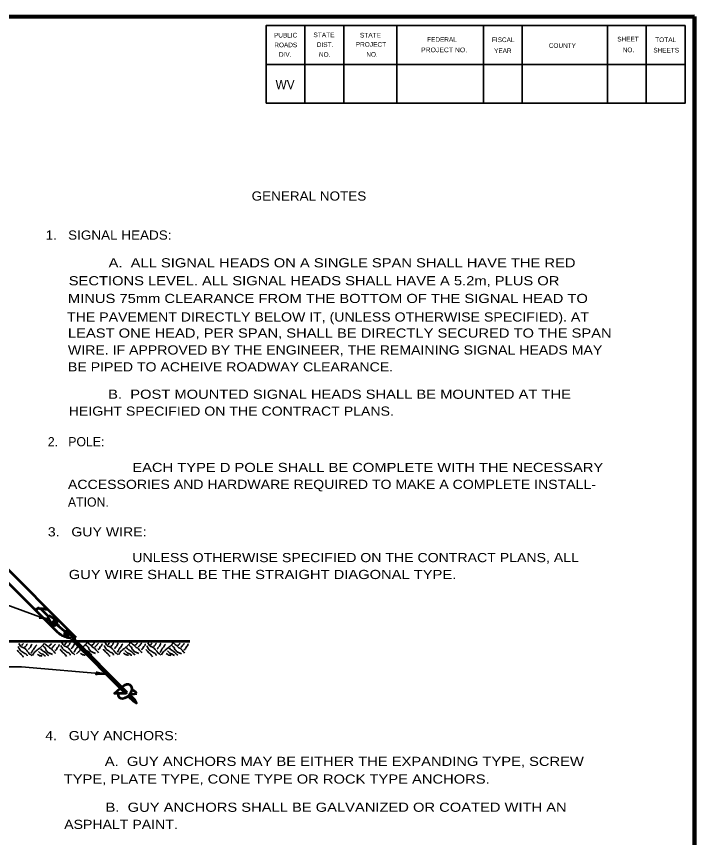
# Model space of a CAD drawing. Extents: x 14808 to 15663, y 10944 to 11488.
# Drawn here: x 15435 to 15656.9, y 11213.1 to 11481.7 of the extents above; entities that cross this region are included whole.
import ezdxf
from ezdxf.enums import TextEntityAlignment as Align

# ---------------------------------------------------------------- set-up
doc = ezdxf.new("R2010")
doc.units = 0
doc.header["$LTSCALE"] = 1.2
doc.layers.add('1', color=7, linetype='Continuous', lineweight=53)
doc.layers.add('61', color=7, linetype='Continuous', lineweight=35)

msp = doc.modelspace()

# ---------------------------------------------------------------- linework, layer by layer
at = {"layer": '1', "lineweight": 158}
msp.add_line((15656.868, 10955.64), (15656.868, 11481.74), dxfattribs=at)
at = {"layer": '1', "lineweight": 13}
msp.add_line((15656.868, 10955.64), (15656.868, 11481.74), dxfattribs=at)
at = {"layer": '1'}
for p, q in [((15428.058, 11304.925), (15454.362, 11278.621)), ((15430.179, 11298.561), (15447.998, 11280.742)), ((15442.831, 11288.076), (15445.377, 11285.53)), ((15445.165, 11285.318), (15445.589, 11285.742)), ((15446.438, 11283.196), (15445.165, 11285.318)), ((15447.71, 11284.469), (15445.589, 11285.742)), ((15447.922, 11284.681), (15446.225, 11282.984)), ((15448.347, 11284.257), (15446.65, 11282.56)), ((15448.347, 11284.257), (15447.922, 11284.681)), ((15446.65, 11282.56), (15446.225, 11282.984)), ((15451.386, 11280.077), (15447.463, 11283.368)), ((15448.093, 11282.84), (15448.977, 11282.428)), ((15452.27, 11279.179), (15451.575, 11279.365)), ((15452.27, 11279.179), (15452.084, 11279.874)), ((15453.326, 11278.561), (15471.145, 11260.742)), ((15267.529, 11277.361), (15491.726, 11277.361)), ((15471.993, 11259.893), (15474.357, 11260.31)), ((15471.993, 11259.893), (15473.69, 11258.196))]:
    msp.add_line(p, q, dxfattribs=at)
at = {"layer": '1', "lineweight": 35}
for p, q in [((15445.843, 11284.188), (15421.629, 11293.001)), ((15436.634, 11269.019), (15431.481, 11269.019)), ((15436.634, 11269.019), (15464.409, 11266.59))]:
    msp.add_line(p, q, dxfattribs=at)
at = {"layer": '1', "lineweight": 158}
msp.add_lwpolyline([(15656.868, 11481.74), (14865.168, 11481.64), (14865.268, 10955.64)], dxfattribs=at)
at = {"layer": '1'}
for points in [[(15452.882, 11278.117), (15470.701, 11260.298), (15467.101, 11260.298), (15469.002, 11261.974)], [(15471.549, 11259.449), (15473.246, 11257.752), (15474.317, 11257.126), (15473.69, 11258.196)]]:
    msp.add_lwpolyline(points, dxfattribs=at)
for centre, radius, start, end in [((15447.44, 11283.466), 0.904, 230.20411, 39.79589), ((15453.121, 11285.504), 6.994, 222.90975, 254.56822), ((15451.738, 11279.712), 1.064, 22.37581, 247.62419), ((15451.676, 11279.773), 0.42, 13.9871, 256.0129), ((15452.369, 11281.867), 3.305, 251.74116, 268.96028), ((15451.536, 11276.978), 1.762, 40.24577, 64.00426), ((15450.12, 11279.196), 2.761, 358.69833, 19.49446), ((15454.464, 11279.906), 1.762, 205.99574, 229.75423), ((15453.121, 11285.504), 6.994, 272.0576, 280.22035), ((15470.684, 11260.758), 0.461, 272.04039, 357.95961), ((15472.243, 11258.964), 2.506, 32.48706, 78.42981)]:
    msp.add_arc(centre, radius, start, end, dxfattribs=at)
at = {"layer": '1', "lineweight": 40}
for centre, major_axis, ratio, start_param, end_param in [((15444.499, 11284.324), (2.078, -0.557), 0.122415, 0.8963533, 3.1415927), ((15444.499, 11284.324), (2.078, -0.557), 0.122415, 0.8963533, 3.1415927), ((15444.666, 11284.886), (-1.909, 0.919), 0.07063, 6.2823074, 8.5597026), ((15444.666, 11284.886), (-1.909, 0.919), 0.07063, 6.2823074, 8.5597026), ((15463.076, 11266.374), (2.151, 0), 0.122415, 0.8963533, 3.1415927), ((15463.092, 11266.96), (-2.081, 0.394), 0.07063, 6.2823074, 8.5597026)]:
    msp.add_ellipse(centre, major_axis=major_axis, ratio=ratio, start_param=start_param, end_param=end_param, dxfattribs=at)
at = {"layer": '1'}
msp.add_ellipse((15470.499, 11260.944), major_axis=(-1.919, -1.919), ratio=0.663245, start_param=5.5824837, end_param=10.8796755, dxfattribs=at)
msp.add_spline([(15441.21, 11287.53), (15441.482, 11287.933), (15441.643, 11287.797), (15441.965, 11288.119), (15442.138, 11288.28), (15442.534, 11288.119), (15443.041, 11288.045), (15443.301, 11288.082), (15443.672, 11287.872), (15443.87, 11288.107), (15444.266, 11287.971), (15444.625, 11287.872), (15445.028, 11287.954)], degree=3, dxfattribs=at)
at = {"layer": '1', "lineweight": 35}
for points in [[(15435.808, 11276.655), (15436.575, 11275.58), (15437.574, 11275.119), (15438.188, 11274.505), (15438.495, 11274.121), (15438.879, 11273.66), (15439.186, 11273.276), (15439.646, 11273.046), (15440.03, 11272.586)], [(15437.19, 11276.569), (15437.074, 11276.415), (15437.036, 11276.415), (15436.959, 11276.338), (15436.767, 11275.993), (15436.729, 11275.916)], [(15438.61, 11276.53), (15438.38, 11276.338), (15438.303, 11276.146), (15438.226, 11275.916), (15438.072, 11275.762), (15437.996, 11275.686), (15437.65, 11275.417)], [(15440.107, 11276.415), (15439.877, 11276.185), (15439.723, 11275.801), (15439.531, 11275.417), (15439.109, 11274.956), (15438.955, 11274.726), (15438.879, 11274.611)], [(15441.604, 11276.185), (15441.258, 11275.801), (15441.067, 11275.379), (15440.76, 11275.033), (15440.529, 11274.688), (15440.299, 11274.419), (15440.184, 11274.15), (15440.03, 11273.881), (15439.838, 11273.498)], [(15443.907, 11276.655), (15443.907, 11276.501), (15443.83, 11276.271), (15443.677, 11276.117), (15443.523, 11275.964), (15443.216, 11275.657), (15442.986, 11275.426), (15442.295, 11274.889), (15441.911, 11274.582), (15441.143, 11273.968), (15440.836, 11273.66), (15440.683, 11273.43), (15440.452, 11273.123), (15440.222, 11272.739)], [(15444.176, 11276.616), (15444.79, 11276.079), (15445.328, 11275.618), (15446.249, 11274.927), (15446.479, 11274.85), (15446.71, 11274.543), (15447.093, 11274.083), (15447.554, 11273.622), (15447.784, 11273.315)], [(15445.558, 11275.762), (15446.095, 11276.146), (15446.21, 11276.3), (15446.402, 11276.569)], [(15446.594, 11275.225), (15447.017, 11275.532), (15447.285, 11275.916), (15447.362, 11276.031), (15447.516, 11276.185), (15447.746, 11276.453)], [(15447.592, 11274.342), (15448.13, 11274.649), (15448.207, 11274.995), (15448.706, 11275.609), (15448.859, 11275.801), (15448.936, 11276.108), (15448.974, 11276.262)], [(15449.598, 11275.983), (15449.751, 11275.522), (15450.058, 11275.023), (15450.442, 11274.524), (15450.826, 11274.294), (15451.479, 11273.833), (15452.515, 11273.142), (15452.553, 11272.835)], [(15449.866, 11276.952), (15450.634, 11275.877), (15451.632, 11275.416), (15452.246, 11274.802), (15452.553, 11274.418), (15452.937, 11273.957), (15453.244, 11273.574), (15453.705, 11273.343), (15454.089, 11272.882)], [(15451.248, 11276.866), (15451.133, 11276.712), (15451.095, 11276.712), (15451.018, 11276.635), (15450.826, 11276.29), (15450.788, 11276.213)], [(15452.669, 11276.827), (15452.438, 11276.635), (15452.361, 11276.443), (15452.285, 11276.213), (15452.131, 11276.059), (15452.054, 11275.983), (15451.709, 11275.714)], [(15454.166, 11276.712), (15453.935, 11276.482), (15453.782, 11276.098), (15453.59, 11275.714), (15453.168, 11275.253), (15453.014, 11275.023), (15452.937, 11274.908)], [(15457.966, 11276.952), (15457.966, 11276.798), (15457.889, 11276.568), (15457.736, 11276.414), (15457.582, 11276.261), (15457.275, 11275.954), (15457.045, 11275.723), (15456.742, 11275.488)], [(15457.736, 11276.021), (15457.966, 11275.868), (15458.196, 11275.676), (15458.619, 11275.138), (15458.657, 11274.793), (15458.964, 11274.524), (15459.079, 11274.332), (15459.847, 11273.756), (15460.308, 11273.603), (15460.423, 11273.526), (15460.845, 11273.334)], [(15458.235, 11276.913), (15458.849, 11276.376), (15459.386, 11275.915), (15460.308, 11275.224), (15460.538, 11275.147), (15460.768, 11274.84), (15461.152, 11274.38), (15461.613, 11273.919), (15461.843, 11273.612)], [(15459.617, 11276.059), (15460.154, 11276.443), (15460.269, 11276.597), (15460.461, 11276.866)], [(15460.653, 11275.522), (15461.075, 11275.829), (15461.344, 11276.213), (15461.421, 11276.328), (15461.574, 11276.482), (15461.805, 11276.75)], [(15461.651, 11274.639), (15462.189, 11274.946), (15462.265, 11275.292), (15462.764, 11275.906), (15462.918, 11276.098), (15462.995, 11276.405), (15463.033, 11276.559)], [(15463.755, 11275.983), (15463.909, 11275.522), (15464.216, 11275.023), (15464.6, 11274.524), (15464.984, 11274.294), (15465.636, 11273.833), (15466.673, 11273.142), (15466.711, 11272.835)], [(15464.024, 11276.952), (15464.792, 11275.877), (15465.79, 11275.416), (15466.404, 11274.802), (15466.711, 11274.418), (15467.095, 11273.957), (15467.402, 11273.574), (15467.863, 11273.343), (15468.247, 11272.882)], [(15465.406, 11276.866), (15465.291, 11276.712), (15465.252, 11276.712), (15465.176, 11276.635), (15464.984, 11276.29), (15464.945, 11276.213)], [(15466.826, 11276.827), (15466.596, 11276.635), (15466.519, 11276.443), (15466.442, 11276.213), (15466.289, 11276.059), (15466.212, 11275.983), (15465.866, 11275.714)], [(15468.323, 11276.712), (15468.093, 11276.482), (15467.939, 11276.098), (15467.747, 11275.714), (15467.325, 11275.253), (15467.172, 11275.023), (15467.095, 11274.908)], [(15469.82, 11276.482), (15469.475, 11276.098), (15469.283, 11275.676), (15468.976, 11275.33), (15468.746, 11274.985), (15468.515, 11274.716), (15468.4, 11274.447), (15468.246, 11274.178), (15468.055, 11273.795)], [(15472.124, 11276.952), (15472.124, 11276.798), (15472.047, 11276.568), (15471.893, 11276.414), (15471.74, 11276.261), (15471.433, 11275.954), (15471.202, 11275.723), (15470.511, 11275.186), (15470.127, 11274.879), (15469.36, 11274.265), (15469.053, 11273.957), (15468.899, 11273.727), (15468.669, 11273.42), (15468.438, 11273.036)], [(15471.893, 11276.021), (15472.124, 11275.868), (15472.354, 11275.676), (15472.776, 11275.138), (15472.815, 11274.793), (15473.122, 11274.524), (15473.237, 11274.332), (15474.005, 11273.756), (15474.465, 11273.603), (15474.58, 11273.526), (15475.003, 11273.334)], [(15472.392, 11276.913), (15473.006, 11276.376), (15473.544, 11275.915), (15474.465, 11275.224), (15474.695, 11275.147), (15474.926, 11274.84), (15475.31, 11274.38), (15475.77, 11273.919), (15476.001, 11273.612)], [(15473.774, 11276.059), (15474.312, 11276.443), (15474.427, 11276.597), (15474.619, 11276.866)], [(15474.811, 11275.522), (15475.233, 11275.829), (15475.502, 11276.213), (15475.578, 11276.328), (15475.732, 11276.482), (15475.962, 11276.75)], [(15475.809, 11274.639), (15476.346, 11274.946), (15476.423, 11275.292), (15476.922, 11275.906), (15477.075, 11276.098), (15477.152, 11276.405), (15477.191, 11276.559)], [(15477.715, 11275.884), (15477.868, 11275.423), (15478.176, 11274.924), (15478.559, 11274.425), (15478.943, 11274.195), (15479.596, 11273.734), (15480.632, 11273.043), (15480.671, 11272.736)], [(15477.984, 11276.853), (15478.751, 11275.778), (15479.749, 11275.317), (15480.364, 11274.703), (15480.671, 11274.319), (15481.055, 11273.858), (15481.362, 11273.475), (15481.822, 11273.244), (15482.206, 11272.784)], [(15479.365, 11276.767), (15479.25, 11276.613), (15479.212, 11276.613), (15479.135, 11276.536), (15478.943, 11276.191), (15478.905, 11276.114)], [(15480.786, 11276.728), (15480.556, 11276.536), (15480.479, 11276.344), (15480.402, 11276.114), (15480.248, 11275.96), (15480.172, 11275.884), (15479.826, 11275.615)], [(15482.283, 11276.613), (15482.053, 11276.383), (15481.899, 11275.999), (15481.707, 11275.615), (15481.285, 11275.154), (15481.131, 11274.924), (15481.055, 11274.809)], [(15483.78, 11276.383), (15483.435, 11275.999), (15483.243, 11275.577), (15482.936, 11275.231), (15482.705, 11274.886), (15482.475, 11274.617), (15482.36, 11274.348), (15482.206, 11274.079), (15482.014, 11273.696)], [(15486.083, 11276.853), (15486.083, 11276.699), (15486.006, 11276.469), (15485.853, 11276.315), (15485.699, 11276.162), (15485.392, 11275.855), (15485.162, 11275.624), (15484.471, 11275.087), (15484.087, 11274.78), (15483.319, 11274.166), (15483.012, 11273.858), (15482.859, 11273.628), (15482.628, 11273.321), (15482.398, 11272.937)], [(15485.853, 11275.922), (15486.083, 11275.769), (15486.314, 11275.577), (15486.736, 11275.039), (15486.774, 11274.694), (15487.081, 11274.425), (15487.196, 11274.233), (15487.964, 11273.657), (15488.425, 11273.504), (15488.54, 11273.427), (15488.962, 11273.235)], [(15486.352, 11276.814), (15486.966, 11276.277), (15487.504, 11275.816), (15488.425, 11275.125), (15488.655, 11275.048), (15488.886, 11274.741), (15489.269, 11274.281), (15489.73, 11273.82), (15489.96, 11273.513)], [(15487.734, 11275.96), (15488.271, 11276.344), (15488.386, 11276.498), (15488.578, 11276.767)], [(15488.77, 11275.423), (15489.193, 11275.73), (15489.461, 11276.114), (15489.538, 11276.229), (15489.692, 11276.383), (15489.922, 11276.651)], [(15489.768, 11274.54), (15490.306, 11274.847), (15490.383, 11275.193), (15490.882, 11275.807), (15491.035, 11275.999), (15491.112, 11276.306), (15491.15, 11276.46)], [(15435.232, 11274.457), (15435.385, 11274.189), (15435.692, 11273.882), (15436.076, 11273.421), (15436.422, 11273.191), (15436.729, 11272.807), (15437.036, 11272.499), (15437.343, 11272.116)], [(15435.539, 11275.686), (15435.692, 11275.225), (15435.999, 11274.726), (15436.383, 11274.227), (15436.767, 11273.997), (15437.42, 11273.536), (15438.456, 11272.845), (15438.495, 11272.538)], [(15442.18, 11274.035), (15442.679, 11273.574), (15442.871, 11273.421), (15443.216, 11273.191), (15443.907, 11272.922), (15444.138, 11272.653), (15444.483, 11272.499)], [(15442.909, 11274.88), (15443.485, 11274.304), (15443.6, 11274.265), (15443.715, 11274.15), (15444.214, 11273.843), (15444.829, 11273.306), (15445.02, 11272.999), (15445.596, 11272.653)], [(15443.677, 11275.724), (15443.907, 11275.57), (15444.138, 11275.379), (15444.56, 11274.841), (15444.598, 11274.496), (15444.905, 11274.227), (15445.02, 11274.035), (15445.788, 11273.459), (15446.249, 11273.306), (15446.364, 11273.229), (15446.786, 11273.037)], [(15449.291, 11274.754), (15449.444, 11274.486), (15449.751, 11274.178), (15450.135, 11273.718), (15450.481, 11273.488), (15450.788, 11273.104), (15451.095, 11272.797), (15451.402, 11272.413)], [(15455.08, 11275.624), (15454.818, 11275.33), (15454.588, 11274.985), (15454.358, 11274.716), (15454.242, 11274.447), (15454.089, 11274.178), (15453.897, 11273.795)], [(15455.862, 11274.749), (15455.862, 11274.595), (15455.785, 11274.365), (15455.632, 11274.211), (15455.478, 11274.058), (15455.171, 11273.751), (15454.941, 11273.52), (15454.638, 11273.285)], [(15455.893, 11273.411), (15456.162, 11273.257), (15456.661, 11272.912), (15456.738, 11272.873), (15456.968, 11272.873), (15457.467, 11272.797)], [(15456.239, 11274.332), (15456.738, 11273.871), (15456.93, 11273.718), (15457.186, 11273.547)], [(15456.968, 11275.177), (15457.544, 11274.601), (15457.659, 11274.562), (15457.774, 11274.447), (15458.273, 11274.14), (15458.887, 11273.603), (15459.079, 11273.296), (15459.655, 11272.95)], [(15463.448, 11274.754), (15463.602, 11274.486), (15463.909, 11274.178), (15464.293, 11273.718), (15464.638, 11273.488), (15464.945, 11273.104), (15465.252, 11272.797), (15465.559, 11272.413)], [(15470.051, 11273.411), (15470.319, 11273.257), (15470.818, 11272.912), (15470.895, 11272.873), (15471.126, 11272.873), (15471.624, 11272.797)], [(15470.396, 11274.332), (15470.895, 11273.871), (15471.087, 11273.718), (15471.433, 11273.488), (15472.124, 11273.219), (15472.354, 11272.95), (15472.699, 11272.797)], [(15471.126, 11275.177), (15471.701, 11274.601), (15471.816, 11274.562), (15471.932, 11274.447), (15472.431, 11274.14), (15473.045, 11273.603), (15473.237, 11273.296), (15473.812, 11272.95)], [(15477.408, 11274.655), (15477.561, 11274.387), (15477.868, 11274.079), (15478.252, 11273.619), (15478.598, 11273.389), (15478.905, 11273.005), (15479.212, 11272.698), (15479.519, 11272.314)], [(15484.01, 11273.312), (15484.279, 11273.158), (15484.778, 11272.813), (15484.855, 11272.774), (15485.085, 11272.774), (15485.584, 11272.698)], [(15484.356, 11274.233), (15484.855, 11273.772), (15485.047, 11273.619), (15485.392, 11273.389), (15486.083, 11273.12), (15486.314, 11272.851), (15486.659, 11272.698)], [(15485.085, 11275.078), (15485.661, 11274.502), (15485.776, 11274.463), (15485.891, 11274.348), (15486.39, 11274.041), (15487.005, 11273.504), (15487.196, 11273.197), (15487.772, 11272.851)], [(15441.834, 11273.114), (15442.103, 11272.96), (15442.602, 11272.615), (15442.679, 11272.576), (15442.909, 11272.576), (15443.408, 11272.499)]]:
    msp.add_spline(points, degree=3, dxfattribs=at)
at = {"layer": '61'}
for p, q in [((15529.368, 11478.74), (15529.368, 11453.34)), ((15542.068, 11478.74), (15542.068, 11453.34)), ((15559.468, 11478.74), (15559.468, 11453.34)), ((15587.768, 11478.74), (15587.768, 11453.34)), ((15600.468, 11478.74), (15600.468, 11453.34)), ((15628.368, 11478.74), (15628.368, 11453.34)), ((15641.068, 11478.74), (15641.068, 11453.34)), ((15653.768, 11466.04), (15516.668, 11466.04))]:
    msp.add_line(p, q, dxfattribs=at)
for points in [[(15653.768, 11478.74), (15516.668, 11478.74), (15516.668, 11453.34)], [(15653.768, 11478.74), (15653.768, 11453.34), (15516.668, 11453.34)]]:
    msp.add_lwpolyline(points, dxfattribs=at)

# ---------------------------------------------------------------- texts
at = {"layer": '1'}
for s, height, width, p in [('WV', 3.048, 0.95, (15519.768, 11457.94)), ('1.   SIGNAL HEADS:', 3, 1.1, (15444.529, 11408.718)), ('A.  ALL SIGNAL HEADS ON A SINGLE SPAN SHALL HAVE THE RED ', 3, 1.2, (15465.142, 11399.648)), ('SECTIONS LEVEL. ALL SIGNAL HEADS SHALL HAVE A 5.2m, PLUS OR ', 3, 1.2, (15452.102, 11393.779)), ('MINUS 75mm CLEARANCE FROM THE BOTTOM OF THE SIGNAL HEAD TO', 3, 1.2, (15451.839, 11387.988)), ('THE PAVEMENT DIRECTLY BELOW IT, (UNLESS OTHERWISE SPECIFIED). AT ', 3, 1.15, (15451.576, 11381.933)), ('LEAST ONE HEAD, PER SPAN, SHALL BE DIRECTLY SECURED TO THE SPAN ', 3, 1.2, (15451.839, 11376.669)), ('WIRE. IF APPROVED BY THE ENGINEER, THE REMAINING SIGNAL HEADS MAY ', 3, 1.15, (15451.839, 11371.141)), ('BE PIPED TO ACHEIVE ROADWAY CLEARANCE.', 3, 1.15, (15451.839, 11365.613)), ('B.  POST MOUNTED SIGNAL HEADS SHALL BE MOUNTED AT THE', 3, 1.2, (15465.001, 11356.663)), ('HEIGHT SPECIFIED ON THE CONTRACT PLANS.', 3, 1.15, (15452.102, 11351.136)), ('EACH TYPE D POLE SHALL BE COMPLETE WITH THE NECESSARY', 3, 1.2, (15472.897, 11332.71)), ('ACCESSORIES AND HARDWARE REQUIRED TO MAKE A COMPLETE INSTALL-', 3, 1.15, (15451.839, 11327.182)), ('3.   GUY WIRE:', 3, 1.15, (15445.258, 11311.651)), ('UNLESS OTHERWISE SPECIFIED ON THE CONTRACT PLANS, ALL', 3, 1.15, (15472.898, 11303.228)), ('GUY WIRE SHALL BE THE STRAIGHT DIAGONAL TYPE.', 3, 1.2, (15452.102, 11297.7)), ('4.   GUY ANCHORS:', 3, 1.15, (15444.407, 11244.993)), ('A.  GUY ANCHORS MAY BE EITHER THE EXPANDING TYPE, SCREW', 3, 1.2, (15463.886, 11236.57)), ('TYPE, PLATE TYPE, CONE TYPE OR ROCK TYPE ANCHORS.', 3, 1.2, (15450.461, 11230.779)), ('B.  GUY ANCHORS SHALL BE GALVANIZED OR COATED WITH AN ', 3, 1.2, (15464.149, 11221.566)), ('ASPHALT PAINT.', 3, 1.15, (15450.606, 11215.952))]:
    msp.add_text(s, height=height, dxfattribs=dict(at, width=width)).set_placement(p)
at = {"layer": '1', "width": 1.1}
msp.add_text('GENERAL NOTES', height=3, dxfattribs=at).set_placement((15530.693, 11421.498), align=Align.CENTER)
at = {"layer": '1'}
for s, p in [('2.   POLE:', (15445.258, 11341.133)), ('ATION.', (15451.839, 11321.391))]:
    msp.add_text(s, height=3, dxfattribs=at).set_placement(p)
at = {"layer": '61'}
for s, height, rotation, p in [('PUBLIC', 1.525, 0.033, (15519.268, 11474.84)), ('FEDERAL', 1.523, 0.007, (15569.368, 11473.44)), ('FISCAL', 1.525, 359.942, (15590.568, 11473.34)), ('SHEET', 1.525, 0.059, (15631.568, 11473.54)), ('ROADS', 1.525, 0.124, (15519.368, 11471.64)), ('DIST.', 1.525, 0.056, (15533.268, 11471.74)), ('COUNTY', 1.523, 0.069, (15609.168, 11471.44)), ('DIV.', 1.525, 359.932, (15520.868, 11468.54)), ('YEAR', 1.523, 0.105, (15591.268, 11469.74)), ('SHEETS', 1.523, 359.959, (15643.368, 11469.94))]:
    msp.add_text(s, height=height, rotation=rotation, dxfattribs=at).set_placement(p)
for s, rotation, width, p in [('STATE', 0.059, 1.05, (15532.168, 11474.94)), ('STATE', 0.059, 1.05, (15547.368, 11474.84)), ('TOTAL', 359.926, 1.05, (15643.968, 11473.34)), ('PROJECT', 359.908, 1.05, (15545.968, 11471.84)), ('NO.', 359.852, 0.9, (15533.968, 11468.54)), ('NO.', 0.225, 0.9, (15549.468, 11468.54)), ('PROJECT NO.', 359.922, 1.1, (15567.368, 11470.04)), ('NO.', 359.852, 0.9, (15633.368, 11470.04))]:
    msp.add_text(s, height=1.525, rotation=rotation, dxfattribs=dict(at, width=width)).set_placement(p)

doc.saveas('drawing.dxf')
